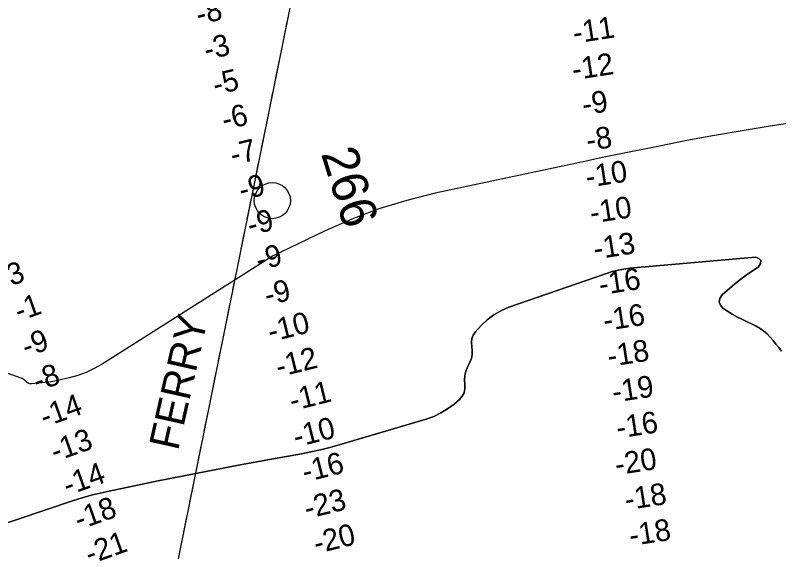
# Model space of a CAD drawing. Extents: x 3245246 to 3283090, y 806824 to 832173.
# Drawn here: x 3260297 to 3262410, y 820069 to 821555 of the extents above; entities that cross this region are included whole.
import ezdxf

# ---------------------------------------------------------------- set-up
doc = ezdxf.new("R2010")
doc.units = 0
for name, color, linetype in [('V-RIVR-FERY', 7, 'Continuous'), ('V-RIVR-FERY-IDEN', 7, 'Continuous'), ('V-RIVR-IDEN', 7, 'Continuous'), ('V-RIVR-MILE', 7, 'Continuous'), ('V-RIVR-RANG', 7, 'Continuous'), ('V-TOPO-DPTH', 7, 'Continuous'), ('V-TOPO-MINR', 7, 'Continuous')]:
    doc.layers.add(name, color=color, linetype=linetype)

msp = doc.modelspace()

# ---------------------------------------------------------------- linework, layer by layer
at = {"layer": 'V-RIVR-FERY'}
for points in [[(3260522.1, 818934), (3261392, 823224.9)], [(3261038.2, 821479.7), (3261049.8, 821536.8)], [(3261018.3, 821381.8), (3261029.9, 821438.9)], [(3260998.5, 821283.8), (3261010.1, 821341)], [(3260978.6, 821185.9), (3260990.2, 821243.1)], [(3260958.8, 821088), (3260970.4, 821145.2)], [(3260938.9, 820990.1), (3260950.5, 821047.3)], [(3260919.1, 820892.2), (3260930.7, 820949.4)], [(3260899.2, 820794.3), (3260910.8, 820851.4)], [(3260879.4, 820696.4), (3260891, 820753.5)], [(3260859.5, 820598.5), (3260871.1, 820655.6)], [(3260839.7, 820500.6), (3260851.3, 820557.7)], [(3260819.8, 820402.7), (3260831.4, 820459.8)], [(3260800, 820304.8), (3260811.6, 820361.9)], [(3260780.1, 820206.9), (3260791.7, 820264)], [(3260760.3, 820108.9), (3260771.9, 820166.1)]]:
    msp.add_lwpolyline(points, dxfattribs=at)
at = {"layer": 'V-RIVR-MILE'}
msp.add_circle((3261008.4, 821041.7), 50, dxfattribs=at)
at = {"layer": 'V-TOPO-DPTH'}
for points in [[(3262418.1, 820624.7), (3262410.4, 820634.5), (3262402.6, 820644.2), (3262394.6, 820653.9), (3262386.7, 820663.5), (3262378.1, 820672.5), (3262369, 820680.6), (3262358.9, 820687.6), (3262348.1, 820693.7), (3262308, 820713.3), (3262294.6, 820720.2), (3262281.4, 820727.5), (3262268.6, 820735.3), (3262255.9, 820743.5), (3262249, 820752.4), (3262245.7, 820761.5), (3262247.8, 820770.9), (3262253.6, 820780.6), (3262268.3, 820793.7), (3262287.3, 820809.8), (3262306.8, 820825.4), (3262327, 820840), (3262347.6, 820854), (3262354.8, 820858.7), (3262359.8, 820867.8), (3262360.7, 820875.5), (3262355.3, 820881.1), (3262345.7, 820885.2), (3261998.3, 820854.2), (3261981.8, 820852.2), (3261965.5, 820849.3), (3261949.4, 820845.2), (3261933.6, 820840.3), (3261662.8, 820746.2), (3261641.5, 820736.9), (3261621.5, 820725.8), (3261603.5, 820711.7), (3261586.6, 820695.8), (3261570.8, 820678.2), (3261564.7, 820669.1), (3261560.6, 820659.4), (3261559.6, 820648.9), (3261560.5, 820637.9), (3261562, 820626.6), (3261561.9, 820615.5), (3261559.5, 820604.7), (3261555.5, 820594), (3261548.8, 820580.6), (3261544.3, 820569), (3261541.3, 820557.1), (3261540.7, 820544.9), (3261541.6, 820532.5), (3261541.7, 820520.6), (3261539.6, 820509.6), (3261534.1, 820499.8), (3261526.4, 820490.8), (3261511.7, 820478.3), (3261493.8, 820465.1), (3261475.1, 820453.5), (3261455.1, 820444.2), (3261434.2, 820436.6), (3261193.6, 820365.4), (3261167.6, 820358.1), (3261141.5, 820351.5), (3261115.2, 820345.7), (3261088.7, 820340.4), (3260990.4, 820322.6), (3260914.7, 820308.6), (3260839.1, 820294.3), (3260763.5, 820279.4), (3260688.1, 820264.3), (3260556.8, 820237.4), (3260531.7, 820231.7), (3260506.8, 820225.5), (3260482.2, 820218.4), (3260457.7, 820210.7), (3259841.5, 820003.5)], [(3259841.5, 820003.5), (3260457.7, 820210.7), (3260482.2, 820218.4), (3260506.8, 820225.5), (3260531.7, 820231.7), (3260556.8, 820237.4), (3260688.1, 820264.3), (3260763.5, 820279.4), (3260839.1, 820294.3), (3260914.7, 820308.6), (3260990.4, 820322.6), (3261088.7, 820340.4), (3261115.2, 820345.7), (3261141.5, 820351.5), (3261167.6, 820358.1), (3261193.6, 820365.4), (3261434.2, 820436.6), (3261455.1, 820444.2), (3261475.1, 820453.5), (3261493.8, 820465.1), (3261511.7, 820478.3), (3261526.4, 820490.8), (3261534.1, 820499.8), (3261539.6, 820509.6), (3261541.7, 820520.6), (3261541.6, 820532.5), (3261540.7, 820544.9), (3261541.3, 820557.1), (3261544.3, 820569), (3261548.8, 820580.6), (3261555.5, 820594), (3261559.5, 820604.7), (3261561.9, 820615.5), (3261562, 820626.6), (3261560.5, 820637.9), (3261559.6, 820648.9), (3261560.6, 820659.4), (3261564.7, 820669.1), (3261570.8, 820678.2), (3261586.6, 820695.8), (3261603.5, 820711.7), (3261621.5, 820725.8), (3261641.5, 820736.9), (3261662.8, 820746.2), (3261933.6, 820840.3), (3261949.4, 820845.2), (3261965.5, 820849.3), (3261981.8, 820852.2), (3261998.3, 820854.2), (3262345.7, 820885.2), (3262355.3, 820881.1), (3262360.7, 820875.5), (3262359.8, 820867.8), (3262354.8, 820858.7), (3262347.6, 820854), (3262327, 820840), (3262306.8, 820825.4), (3262287.3, 820809.8), (3262268.3, 820793.7), (3262253.6, 820780.6), (3262247.8, 820770.9), (3262245.7, 820761.5), (3262249, 820752.4), (3262255.9, 820743.5), (3262268.6, 820735.3), (3262281.4, 820727.5), (3262294.6, 820720.2), (3262308, 820713.3), (3262348.1, 820693.7), (3262358.9, 820687.6), (3262369, 820680.6), (3262378.1, 820672.5), (3262386.7, 820663.5), (3262394.6, 820653.9), (3262402.6, 820644.2), (3262410.4, 820634.5), (3262418.1, 820624.7)]]:
    msp.add_lwpolyline(points, dxfattribs=at)
at = {"layer": 'V-TOPO-MINR'}
for points in [[(3262611, 821282.1), (3262386.4, 821247.6), (3262309.6, 821235.3), (3262232.9, 821222.2), (3262156.4, 821208), (3262080.1, 821193), (3261972.9, 821171.3), (3261950.2, 821166.6), (3261927.5, 821161.9), (3261904.9, 821157.2), (3261882.2, 821152.4), (3261458.8, 821062.1), (3261380.7, 821042.5), (3261303.7, 821019.2), (3261228.6, 820990.5), (3261154.8, 820958.1), (3261009, 820887.9), (3260537.2, 820588.8), (3260515.4, 820576.5), (3260493, 820565.8), (3260469.6, 820557.4), (3260445.5, 820550.6), (3260413.4, 820543.3), (3260404.9, 820541.5), (3260396.3, 820539.9), (3260387.7, 820538.7), (3260379, 820537.7), (3260341.6, 820533.9), (3260339.1, 820533.9), (3260336.6, 820534.3), (3260334.3, 820535.2), (3260332, 820536.5), (3260329.9, 820538.1), (3260327.8, 820539.8), (3260325.8, 820541.5), (3260323.8, 820543.3), (3260323.4, 820543.7), (3260321.1, 820545.6), (3260318.7, 820547.3), (3260316.1, 820548.6), (3260313.4, 820549.8), (3260087.3, 820630.2)], [(3262418.1, 820624.7), (3262410.4, 820634.5), (3262402.6, 820644.2), (3262394.6, 820653.9), (3262386.7, 820663.5), (3262378.1, 820672.5), (3262369, 820680.6), (3262358.9, 820687.6), (3262348.1, 820693.7), (3262308, 820713.3), (3262294.6, 820720.2), (3262281.4, 820727.5), (3262268.6, 820735.3), (3262255.9, 820743.5), (3262249, 820752.4), (3262245.7, 820761.5), (3262247.8, 820770.9), (3262253.6, 820780.6), (3262268.3, 820793.7), (3262287.3, 820809.8), (3262306.8, 820825.4), (3262327, 820840), (3262347.6, 820854), (3262354.8, 820858.7), (3262359.8, 820867.8), (3262360.7, 820875.5), (3262355.3, 820881.1), (3262345.7, 820885.2), (3261998.3, 820854.2), (3261981.8, 820852.2), (3261965.5, 820849.3), (3261949.4, 820845.2), (3261933.6, 820840.3), (3261662.8, 820746.2), (3261641.5, 820736.9), (3261621.5, 820725.8), (3261603.5, 820711.7), (3261586.6, 820695.8), (3261570.8, 820678.2), (3261564.7, 820669.1), (3261560.6, 820659.4), (3261559.6, 820648.9), (3261560.5, 820637.9), (3261562, 820626.6), (3261561.9, 820615.5), (3261559.5, 820604.7), (3261555.5, 820594), (3261548.8, 820580.6), (3261544.3, 820569), (3261541.3, 820557.1), (3261540.7, 820544.9), (3261541.6, 820532.5), (3261541.7, 820520.6), (3261539.6, 820509.6), (3261534.1, 820499.8), (3261526.4, 820490.8), (3261511.7, 820478.3), (3261493.8, 820465.1), (3261475.1, 820453.5), (3261455.1, 820444.2), (3261434.2, 820436.6), (3261193.6, 820365.4), (3261167.6, 820358.1), (3261141.5, 820351.5), (3261115.2, 820345.7), (3261088.7, 820340.4), (3260990.4, 820322.6), (3260914.7, 820308.6), (3260839.1, 820294.3), (3260763.5, 820279.4), (3260688.1, 820264.3), (3260556.8, 820237.4), (3260531.7, 820231.7), (3260506.8, 820225.5), (3260482.2, 820218.4), (3260457.7, 820210.7), (3259841.5, 820003.5)]]:
    msp.add_lwpolyline(points, dxfattribs=at)

# ---------------------------------------------------------------- texts
at = {"layer": 'V-RIVR-FERY-IDEN'}
msp.add_text('FERRY', height=83, rotation=77.2802, dxfattribs=at).set_placement((3260747.2, 820346.8))
at = {"layer": 'V-RIVR-IDEN'}
msp.add_text('266', height=100, rotation=287.3523, dxfattribs=at).set_placement((3261142.6, 821172.3))
at = {"layer": 'V-RIVR-RANG'}
for s, rotation, p in [('-8', 13.9381, (3260804.9, 821527.6)), ('-11', 8.8312, (3261844.8, 821476.5)), ('-3', 13.9381, (3260826.2, 821429.8)), ('-12', 8.8312, (3261842.2, 821375)), ('-5', 13.9381, (3260851.1, 821333)), ('-9', 8.8312, (3261870.3, 821278.2)), ('-6', 13.9381, (3260876.1, 821236.1)), ('-8', 8.8312, (3261881.7, 821178.8)), ('-7', 13.9381, (3260899.6, 821139)), ('-10', 8.8312, (3261879.9, 821077.4)), ('-9', 13.9381, (3260923.4, 821041.8)), ('-10', 8.8312, (3261892, 820978.1)), ('-9', 13.9381, (3260947, 820944.6)), ('-13', 8.8312, (3261901.9, 820878.5)), ('-9', 13.9381, (3260970.5, 820847.5)), ('-3', 19.5537, (3260260.3, 820796.1)), ('-16', 8.8312, (3261916.8, 820779.7)), ('-9', 13.9381, (3260994.1, 820750.3)), ('-1', 19.5537, (3260306.6, 820706.4)), ('-16', 8.8312, (3261928.8, 820680.4)), ('-10', 13.9381, (3261003.5, 820649.6)), ('-9', 19.5537, (3260326.9, 820607.5)), ('-18', 8.8312, (3261940.4, 820581.1)), ('-12', 13.9381, (3261025.4, 820552)), ('-8', 19.5537, (3260358.1, 820512.5)), ('-19', 8.8312, (3261953.1, 820481.9)), ('-11', 13.9381, (3261063.4, 820458.4)), ('-14', 19.5537, (3260377.7, 820413.3)), ('-16', 8.8312, (3261964.9, 820382.6)), ('-10', 13.9381, (3261074.1, 820358)), ('-13', 19.5537, (3260406.6, 820317.5)), ('-16', 13.9381, (3261098.4, 820261)), ('-20', 8.8312, (3261961.3, 820280.9)), ('-14', 19.5537, (3260441.4, 820223.8)), ('-18', 8.8312, (3261988.5, 820184)), ('-23', 13.9381, (3261104.5, 820159.5)), ('-18', 19.5537, (3260472.6, 820128.7)), ('-20', 13.9381, (3261130.2, 820062.8)), ('-18', 8.8312, (3262000.6, 820084.7)), ('-21', 19.5537, (3260502.4, 820033.2))]:
    msp.add_text(s, height=60, rotation=rotation, dxfattribs=at).set_placement(p)

doc.saveas('drawing.dxf')
